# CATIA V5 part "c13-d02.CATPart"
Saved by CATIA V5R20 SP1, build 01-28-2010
Part number: Part1
Bounding box of the stored display mesh (mm): x -33 to 33, y -200.819 to 48, z -35 to 35
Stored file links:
  D:\v5_r20\psrt_files_downloaded\c13-catia-v5r20-prt\c13-catia-v5r20-figr-13-12 & 13\c13-d02.CATPart
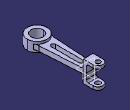
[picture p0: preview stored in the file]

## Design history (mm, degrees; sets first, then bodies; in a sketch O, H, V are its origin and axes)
Body1 (main body)
  Sketch1 on yz-plane, origin (0, 0, 0), H (0, 1, 0), V (0, 0, 1)
    line L1 (0, 0) -> (0, -35)
    point P1 (0, -35)
    line L2 (0, -35) -> (48, -35)
    point P2 (48, -35)
    line L3 (48, -35) -> (48, -25)
    point P3 (48, -25)
    line L4 (48, -25) -> (10, -25)
    point P4 (10, -25)
    line L5 (10, -25) -> (10, 0)
    point P5 (10, 0)
    point P6 (0, 0)
    point P7 (0, 0)
    point P8 (0, 35)
    point P9 (48, 35)
    point P10 (48, 25)
    point P11 (10, 25)
    point P12 (10, 0)
    point P13 (0, 0)
    line L6 (0, 0) -> (0, 35)
    line L7 (0, 35) -> (48, 35)
    line L8 (48, 35) -> (48, 25)
    line L9 (48, 25) -> (10, 25)
    line L10 (10, 25) -> (10, 0)
    length L8 = 10
    distance P3 L9 = 50
    length L2 = 48
    distance L10 L6 = 10
    vertical: L1 V, L3 V, L5 V
    horizontal: L2 H, L4 H
    symmetry: O P7 H, P1 P8 H, P2 P9 H, P3 P10 H, P4 P11 H, P5 P12 H, P6 P13 H, L1 L6 H, L2 L7 H, L3 L8 H, L4 L9 H, L5 L10 H
    coincidence: P13 P7, P12 P5, P6 P7
  Pad1: profile Sketch1, direction (1, 0, 0), length 16, mirrored extent
  Sketch2 on xy-plane, origin (0, 0, 0), H (1, 0, 0), V (0, 1, 0)
    circle A1 centre (0, -168) radius 33
    point P1 (0, -168)
    circle A2 centre (0, -168) radius 20
    distance P1 H = 168
    radius A1 = 33
    radius A2 = 20
    coincidence: P1 V
  Pad2: profile Sketch2, direction (0, 0, 1), length 16, mirrored extent
  Sketch3 on xy-plane, origin (0, 0, 0), H (1, 0, 0), V (0, 1, 0)
    line L1 (-16, 0) -> (-25, -146.4593)
    point P1 (-16, 0)
    point P2 (-25, -146.4593)
    line L2 (16, 0) -> (25, -146.4593)
    point P3 (16, 0)
    point P4 (25, -146.4593)
    reference projected line E1 (16, 48) -> (16, 0) from edge [face of Pad1 | face of Pad1]
    reference projected line E2 (-16, 48) -> (-16, 0) from edge [face of Pad1 | face of Pad1]
    projected circle E3 centre (0, -168) radius 33 from edge [face of Pad2 | face of Pad2]
    projected arc E4 centre (0, -168) radius 33 from (25, -146.4593) to (-25, -146.4593) ccw from edge [face of Pad2 | face of Pad2]
    line L3 (-16, 0) -> (16, 0)
    distance P4 P2 H = 50
    coincidence: P1 H, P3 H, P3 E1, P1 E2, P2 E3, P4 E3
    symmetry: P4 P2 V
    horizontal: L3 H
  Pad3: profile Sketch3, direction (0, 0, 1), length 8, mirrored extent
  Fillet1: radius 6, on edge [face of Pad1 | face of Pad3]; edge [face of Pad3 | face of Pad1]; edge [face of Pad1 | face of Pad1] (x2)
  Fillet2: radius 30, on edge [face of Pad3 | face of Pad2]; edge [face of Pad2 | face of Pad3]
  TritangentFillet1: Face1 face of Pad1, RemoveFace face of Pad1, Face2 face of Pad1
  TritangentFillet2: Face1 face of Pad1, RemoveFace face of Pad1, Face2 face of Pad1
  Sketch4 on face of Pad1, origin (2.8418, 32, 35), H (1, 0, 0), V (0, 1, 0)
    point P1 (-2.8418, 0)
    reference projected arc E1 centre (-2.8418, 0) radius 16 from (13.1582, 0) to (-18.8418, 0) ccw from edge [face of Pad1 | face of TritangentFillet1]
    concentricity: P1 E1
  Hole1: placed by Sketch4, at (0, 32, 35) direction (0, 0, -1), diameter 16, through (limit type 3)
  Sketch5 on face of Pad3, origin (0, 0, 8), H (1, 0, 0), V (0, 1, 0)
    construction line L1 (0, -25) -> (0, -115)
    point P1 (0, -25)
    line L2 (7, -25) -> (7, -115)
    line L3 (-7, -115) -> (-7, -25)
    arc A1 centre (0, -115) radius 7 from (7, -115) to (-7, -115) cw
    arc A2 centre (0, -25) radius 7 from (-7, -25) to (7, -25) cw
    distance P1 H = 25
    length L1 = 90
    radius A1 = 7
    coincidence: P1 V
    vertical: L1 V
    tangency: A1 L2, A2 L2, A1 L3, A2 L3
    parallelism: L1 L2
  Pocket1: profile Sketch5, direction (0, 0, -1), through (limit type 3)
